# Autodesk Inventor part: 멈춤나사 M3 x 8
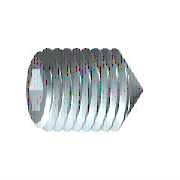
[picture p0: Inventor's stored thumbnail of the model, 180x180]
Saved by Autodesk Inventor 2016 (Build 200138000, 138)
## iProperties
IsCustomPart: 1
Created: 2012-02
Part Number: 멈춤나사 M3 x 8
Material: 강철, 연강
Description: 6각 소켓 머리 없는 멈춤 나사
Document SubType Name: Modeling
Standard: KS B 1028
Designer: test
Standards Organization: KS
Language: ko-KR
Size Designation: 원추점 M3x8
Categories: <MemberInstance><Categories><Category DisplayName="조임쇠" InternalName="e4da775c-781d-43d5-af7c-5136215cf5a6" Mnemonic="FSTN"><Category DisplayName="볼트" InternalN
Density: 1 g/cm^3
Appearance: 강철
Author: test
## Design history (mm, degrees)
sketch "스케치1"
  geometry: L1 (0, 0)-(5.5, 0); L2 (8, 0.866)-(8, 1.5); L3 (8, 1.5)-(0, 1.5); L4 (8, 0.866)-(6, 0.866); L5 (6, 0.866)-(5.5, 0); L6 (0, -0.3)-(0, 1.8) reference; L7 (0, 1.5)-(0, 0)
  constraints: 13 end point, 3 parallel, 1 collinear, 1 perpendicular, 1 point on line
  dimensions: "d0" = 2 distance of L2.start L4.end (= INTI); "d1" = 60 deg angle of L5 L1; "d2" = 3 diameter of L3 L1 (= NND); "d3" = 1.73205 diameter of L4 L1 (= 1.1547 x SW); "d5" = 8 distance from line of L2 L3.end (= NLG)
revolve "본체" sketch "스케치1" stored, may be unused: angle "d6" = 90 deg
sketch "스케치2"
  geometry: L1 (-0.433, 0.75)-(0.433, 0.75); L2 (0.433, 0.75)-(0.866, 0); L3 (0.866, 0)-(0.433, -0.75); L4 (0.433, -0.75)-(-0.433, -0.75); L5 (-0.433, -0.75)-(-0.866, 0); L6 (-0.866, 0)-(-0.433, 0.75); 3 further points
  constraints: 12 end point, 1 coincident, 1 horizontal, 13 other
extrude "슬롯" join sketch "스케치2" taper "d7" = 0 deg; stored distance "d21" = 10
workaxis "Work Axis1"
workplane "Work Plane1"
sketch "스케치4"
  geometry: L1 (0, 0.15)-(-1.35, 1.5) reference; L2 (0, -0.15)-(-1.35, -1.5) reference; L3 (-1.35, -1.5)-(0.15, 0); L4 (-1.35, 1.5)-(0.15, 0); 2 further points
  constraints: 4 end point, 1 coincident, 1 collinear, 1 horizontal alignment
body "Solid1"
feature "스레드" dims "d12" = 8 (= NLG), "d13" = 0
chamfer "모따기1" distance "d8" = 1.35 (computed from NND, SPD, FAWI); stored, may be unused: angle "d9" = 45 deg (= FAWI), second distance "d34" = 1.35 (computed from NND, SPD, FAWI)
chamfer "모따기2" distance "d10" = 0.30673 (= -0.5 x GD1 + 0.5 x NND); stored, may be unused: angle "d11" = 45 deg (= FAWI), second distance "d35" = 0.30673 (= -0.5 x GD1 + 0.5 x NND)
other parameters: "NND" = 3 [user parameter; used in 5 equation terms], "NLG" = 8 [user parameter; used in 2 equation terms], "INTI" = 2 [user parameter; used in 1 equation term], "FAWI" = 45 deg [user parameter; used in 4 equation terms], "SW" = 1.5 [user parameter; used in 2 equation terms], "GD1" = 2.38655 (= THREADDIA - 1.2269 x PTC) [user parameter; used in 2 equation terms], "d4" = 0, "FAWI1" = 45 deg [user parameter], "SPD" = 0.3 [user parameter; used in 2 equation terms], "d36" = 0, "d37" = 0, "GUL" = 0.30673 (= 0.61345 x PTC) [user parameter], "TOA" = 30 deg [user parameter], "THREADDIA" = 3 [user parameter; used in 1 equation term], "PTC" = 0.5 [user parameter; used in 4 equation terms], "GAL" = 0.30673 (= 0.61345 x PTC) [user parameter], "E0" = 1.7325 (= 1.155 x SW) [user parameter]
